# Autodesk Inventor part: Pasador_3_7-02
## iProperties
Company: COMGRAP
Created: 2008-01
Part Number: Pasador_3_7-02
Material: ABS Plastic
Document SubType Name: Modeling
Designer: eruiz-tagle
Mass: 0.76612 g
Surface Area: 8.92429 cm^2
Volume: 0.722755 cm^3
Density: 1.06 g/cm^3
Title: CURSO INVENTOR
Author: Esteban
Comments: Esta pieza fue creada en el curso de inventor
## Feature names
1. Derived Body1 [Tagging]
